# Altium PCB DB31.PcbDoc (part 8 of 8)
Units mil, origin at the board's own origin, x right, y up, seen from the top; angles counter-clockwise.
Board outline 3236.22 x 4456.69 mil, 8 copper layers (Top Layer, MidLayer1, MidLayer2, GND-Layer5, MidLayer3, VCC, MidLayer4, Bottom Layer), stack 61.8 mil thick; 226 components, 469 nets, 1815 pads, 1562 vias.
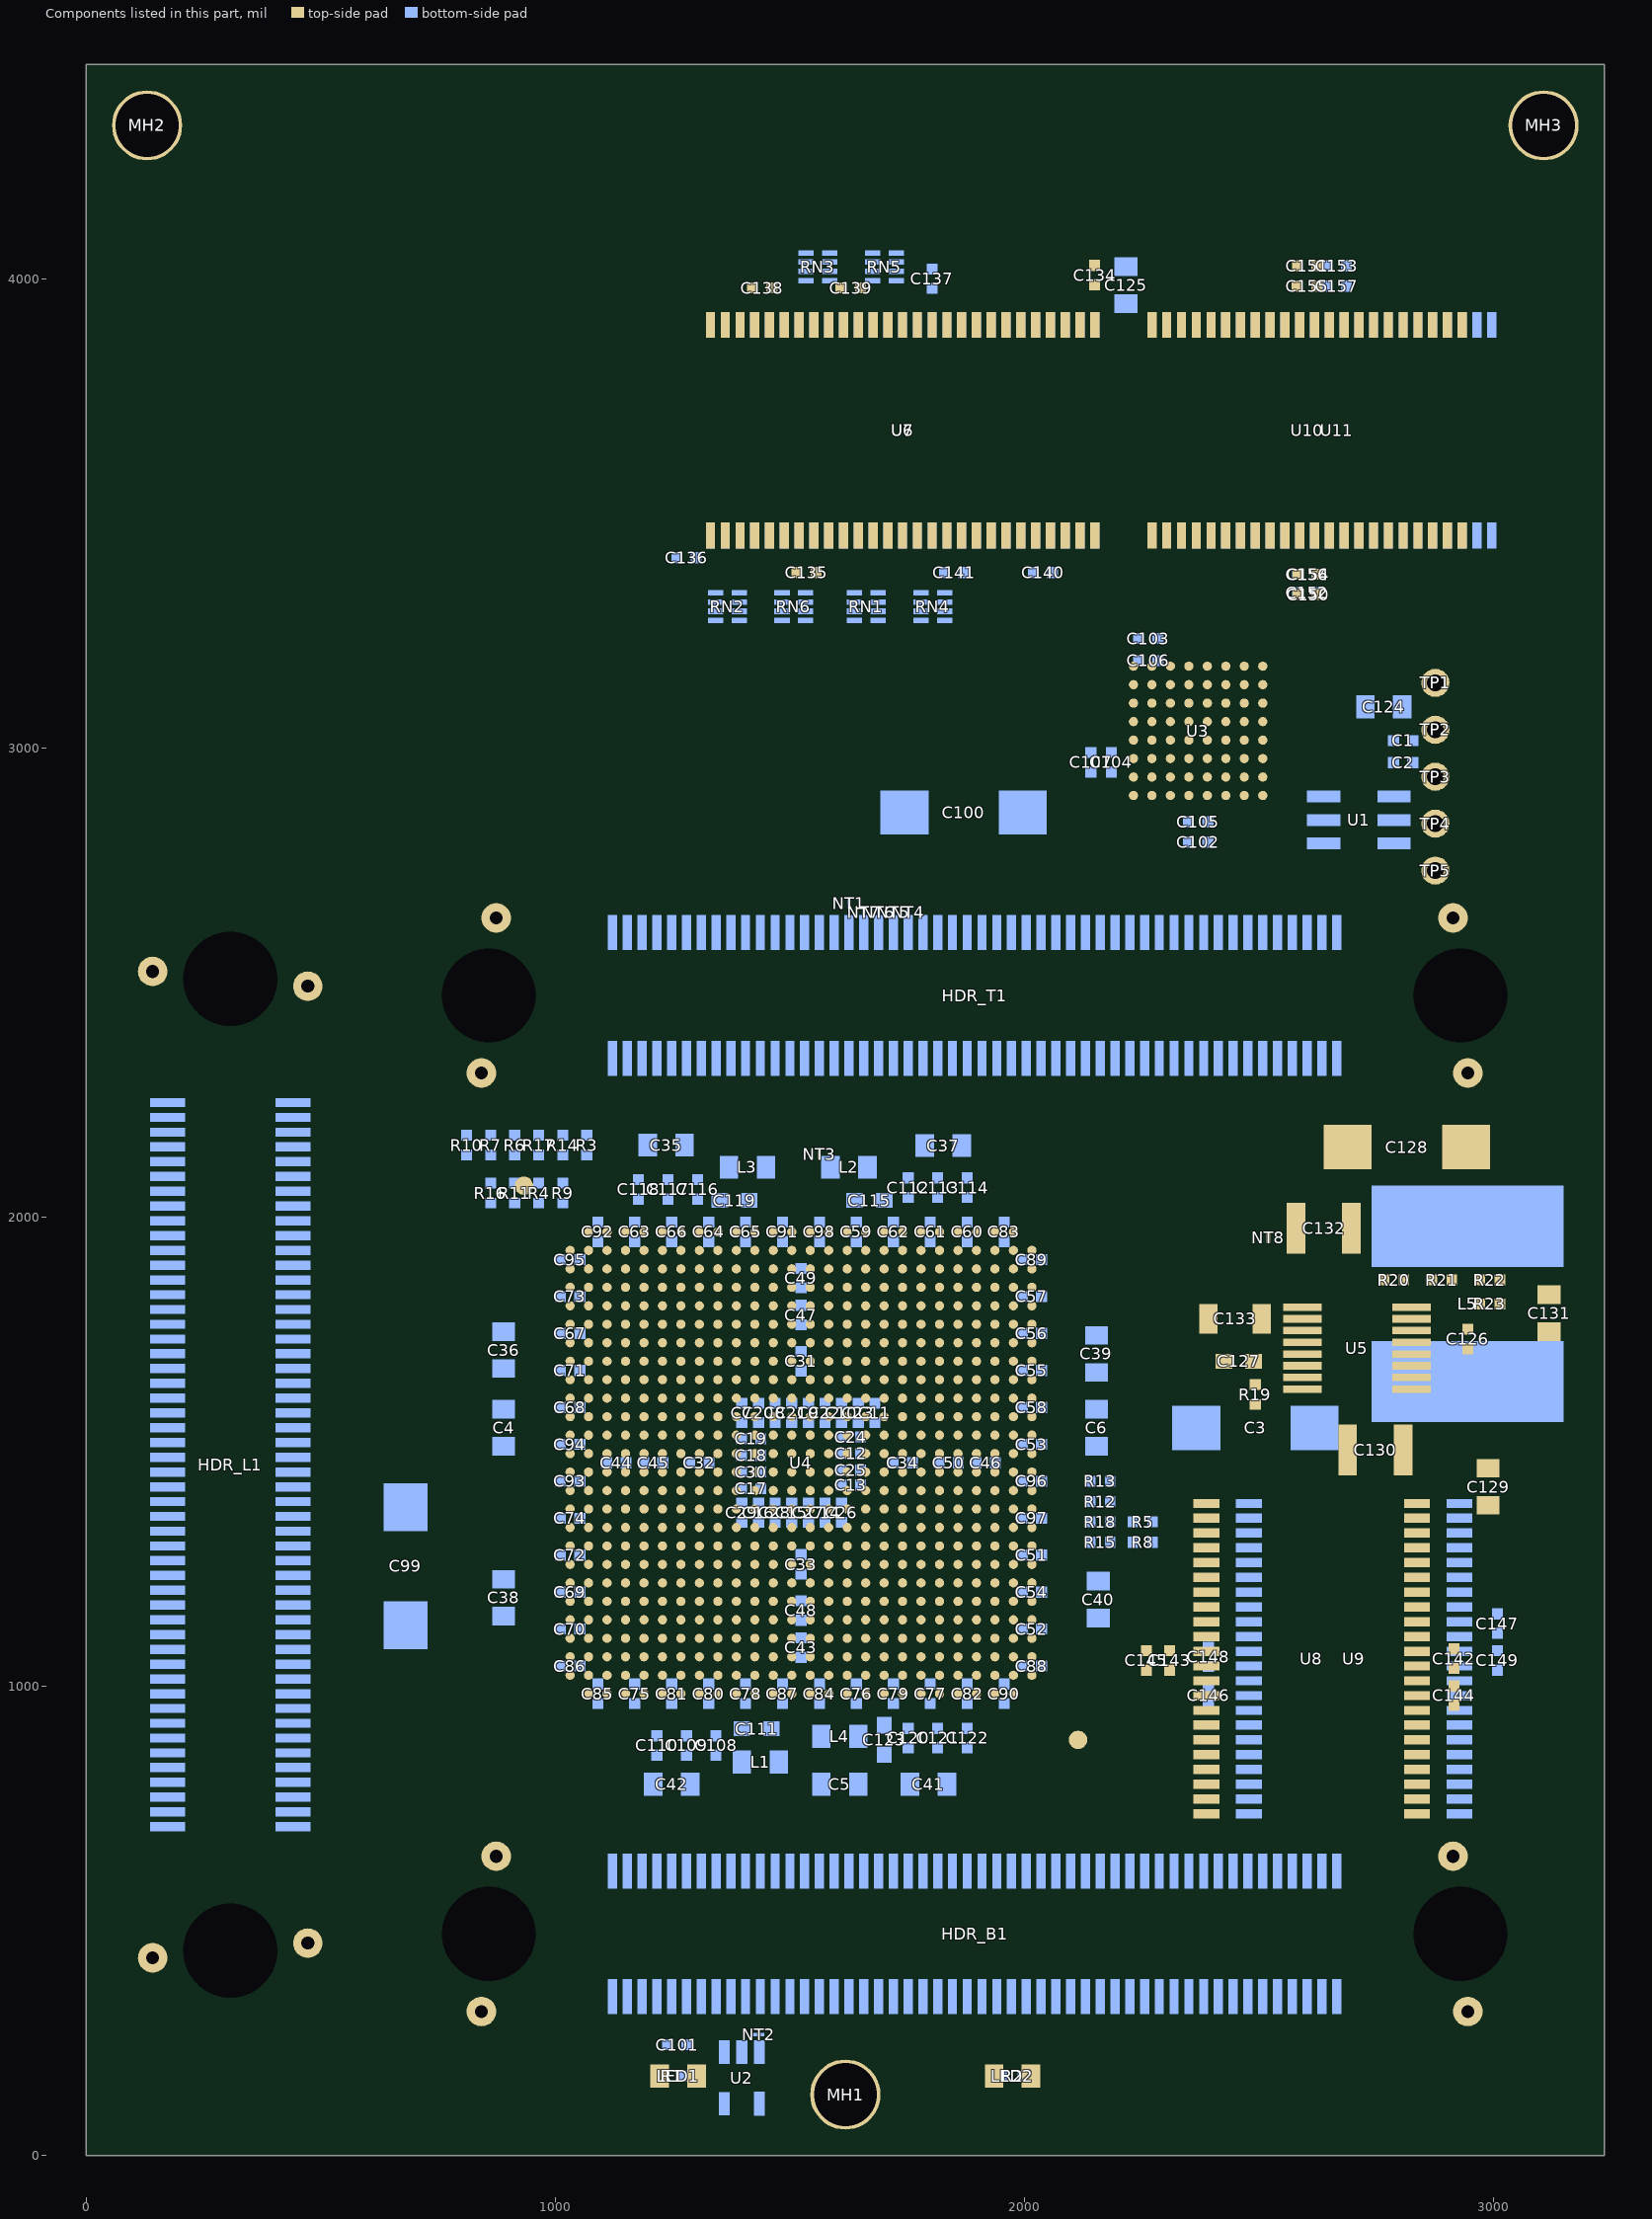
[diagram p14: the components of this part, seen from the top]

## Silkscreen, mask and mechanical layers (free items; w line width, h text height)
Top Overlay:
  region: 146.51,4136.09 139.44,4129.02 164.19,4104.27 171.26,4111.34
  rectangle: 136.51,4026.09 146.51,4136.09
  region: 88.59,4111.34 95.66,4104.27 120.41,4129.02 113.34,4136.09
  region: 123.34,4136.09 113.34,4136.09 113.34,4026.09 123.34,4026.09
  region: 3122.89,4136.09 3115.82,4129.02 3140.56,4104.27 3147.64,4111.34
  rectangle: 3112.89,4026.09 3122.89,4136.09
  region: 3064.97,4111.34 3072.04,4104.27 3096.79,4129.02 3089.71,4136.09
  region: 3099.71,4136.09 3089.71,4136.09 3089.71,4026.09 3099.71,4026.09
  region: 1814.46,159.54 1814.46,169.54 1779.46,169.54 1779.46,159.54
  region: 1772.38,166.61 1779.46,159.54 1857.24,237.33 1850.17,244.4
  rectangle: 1756,183 1766,218
  region: 1840.85,253.71 1833.78,260.78 1756,183 1763.07,175.93
  region: 2787.4,695.23 2787.4,1424.21 2694.88,1424.21 2694.88,695.23
  rectangle: 1337.26,129.92 1351.38,208.66
  rectangle: 2049.67,129.92 2063.98,208.66
  rectangle: 1301.18,3503.94 2179.13,3596.46
  rectangle: 2238.19,3502.95 2966.89,3595.47
  region: 1073.79,617.74 998.77,617.74 998.77,318.48 1073.79,318.48
  rectangle: 2715.79,318.48 2788.79,617.48
  rectangle: 998.77,318.48 1627.79,354.48
  rectangle: 998.77,581.74 1627.79,617.74
  region: 1579.72,4181.1 1579.72,4456.69 1576.77,4456.69 1576.77,4181.1
  region: 1664.37,4181.1 1664.37,4456.69 1649.61,4456.69 1649.61,4181.1
  region: 1640.75,4181.1 1640.75,4456.69 1628.94,4456.69 1628.94,4181.1
  region: 1618.11,4181.1 1618.11,4456.69 1610.24,4456.69 1610.24,4181.1
  region: 1598.43,4181.1 1598.43,4456.69 1593.51,4456.69 1593.51,4181.1
  region: 1689.96,4181.1 1689.96,4456.69 1670.28,4456.69 1670.28,4181.1
  region: 2984.25,4181.1 2984.25,4213.58 1693.9,4213.58 1693.9,4181.1
  region: 2968.5,4438.98 2968.5,4456.69 1693.9,4456.69 1693.9,4438.98
  region: 1803.15,4447.83 1693.9,4447.83 1693.9,4181.1 1803.15,4181.1
  region: 1699.8,4318.9 1699.8,4199.8 1968.5,4199.8 1968.5,4318.9
  rectangle: 2925.2,4181.1 2980.31,4456.69
  rectangle: 2980.31,4181.1 3232.28,4200.79
  rectangle: 2755.91,4204.72 2980.31,4318.9
  rectangle: 2736.22,1620.75 2763.78,1820.75
  lines w3: 1118.09,192.91 1133.09,202.91 1123.09,202.91 1143.09,217.91 ; 1133.09,207.91 1143.09,217.91 ; 1133.09,212.91 1143.09,217.91 ; 2137.52,187.01 2152.52,197.01 2142.52,197.01 2162.52,212.01 ; 2152.52,202.01 2162.52,212.01 ; 2152.52,207.01 2162.52,212.01
  lines w5: 1078.13,171.78 1103.06,171.78 ; 1103.06,173.36 1126.68,173.36 ; 1104.64,163.12 1126.68,172.05 ; 1104.64,180.97 1126.68,172.05 ; 1105.03,168.63 1126.68,172.96 ; 1105.03,175.46 1126.68,171.13 ; 1126.68,156.3 1126.68,187.79 ; 1126.68,171.78 1150.04,171.78 ; 2097.56,165.88 2122.48,165.88 ; 2122.48,167.45 2146.1,167.45 ; 2124.06,157.21 2146.1,166.14 ; 2124.06,175.07 2146.1,166.14 ; 2124.45,162.73 2146.1,167.06 ; 2124.45,169.56 2146.1,165.23 ; 2146.1,150.39 2146.1,181.89 ; 2146.1,165.88 2169.46,165.88 ; 2260.08,1094.39 2280.3,1122.24 ; 2288.68,987.98 2308.9,1015.83 ; 1126.68,172.05 1103.06,187.79 1103.06,156.3 1126.68,172.05 ; 2146.1,166.14 2122.48,150.39 2122.48,181.89 2146.1,166.14
  lines w7.87: 3232.28,4185.04 3232.28,4200.79 ; 3232.28,4200.79 3232.28,4452.76 2980.31,4452.76 2980.31,4200.79 3232.28,4200.79
  text "Altera®  Cyclone™ II" at 1807.26,4342.52 h125.98
  text "EP2C35F672C8" at 1980.49,4216.54 h118.11
  text "SRAM-256Kx16" at 2345.44,3699.95 h50
  text "DRAM-16Mx16" at 1482.53,3682.61 h50
  text "FLASH" at 2491.1,2767.2 h34
  text "1831" at 2721.4,1671.7 h40 r90
  text "SRAM-256Kx16" at 2589.13,807.8 h50 r90
  text "DB31.07" at 1027.8,488.46 h98.43
  text "EP2C35F672C8" at 1027.8,430.47 h60
  text "Altera Daughter Board" at 1028.31,354.49 h60
  text "DB31.07" at 1625.79,318.46 h60
  text "PROGRAM" at 1145,60 h55.12
  text "POWER" at 1895,60 h55.12
Bottom Overlay:
  drawing of 1221 lines, arcs and shapes, not listed
  text "Altera®  Cyclone™ II" at 2905.38,4344.42 h125.98
  text "EP2C35F672C8" at 2732.16,4218.44 h118.11
  text "MANUFACTURE" at 1006.78,3830.86 h40
  text "DATE" at 1007.88,3764.06 h40
  text "SRAM-256Kx16" at 2940.57,3704.01 h50
  text "DRAM-16Mx16" at 1997.78,3682.61 h50
  text "COMPLIANCE:" at 1182.36,3081.45 h45
  text "CLASS 2" at 432.36,2991.45 h40
  text "IPC-A-600H" at 1092.36,2991.45 h40
  text "CLASS 2" at 432.36,2911.45 h40
  text "TYPE 3" at 682.36,2911.45 h40
  text "IPC-6012D" at 1092.36,2911.45 h40
  text "DS2406" at 2711.2,2774.8 h28 r270
  text "1" at 116.93,2272.44 h40
  text "SRAM-256Kx16" at 2733.32,788.17 h50 r270
  text "1" at 1070.87,255.91 h40
  text "DB31" at 412.16,123.67 h120
Bottom Solder:
  region: 2455.79,1920.32 2455.79,2040.32 2305.79,2040.32 2305.79,1920.32
PCB Boundary:
  lines w3.94: 1523.62,4456.69 3236.22,4456.69 ; 1523.62,4456.69 3236.22,4456.69 ; 1523.62,4456.69 0,4456.69 0,0 1618.11,0 3236.22,0 3236.22,4456.69 ; 1523.62,4456.69 3236.22,4456.69 ; 1523.62,4456.69 3236.22,4456.69
Mechanical 7:
  lines w7.87: 2425.71,1720.19 2249.13,1847.52 2249.13,2044.37 2425.71,2171.7 ; 2499.41,1746.69 2322.83,1874.02 2322.83,2070.87 2499.41,2198.19 ; 2575.91,1945.94 2654.65,1945.94 ; 2615.28,1906.57 2615.28,1985.32 ; 2649.61,1972.44 2728.35,1972.44 ; 2688.98,1933.07 2688.98,2011.81 ; 2808.78,1720.19 2985.35,1847.52 2985.35,2044.37 2808.78,2171.7 ; 2882.48,1746.69 3059.06,1874.02 3059.06,2070.87 2882.48,2198.19
Keep Away From Edge:
  lines w7.87: 200,200 3030,200 3030,4250 200,4250 200,200

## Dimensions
307.09,437.01 to 858.27,472.44 on Dimensions
2929.13,472.44 to 2929.13,2472.44 on Dimensions
3106.3,4326.77 to 3236.22,0 on Dimensions
129.92,4342.52 to 0,15.75 on Dimensions
307.09,-15.75 to 0,4275.59 on Dimensions
3236.22,0 to 0,4059.06 on Dimensions
0,4456.69 to -19.69,0 on Dimensions
2929.14,472.44 to 3236.22,-3.94 on Dimensions
1618.11,129.92 to 3236.22,19.69 on Dimensions
307.09,437.01 to -19.69,0 on Dimensions
1618.11,129.92 to 3244.09,0 on Dimensions
2929.14,472.44 to 3244.09,0 on Dimensions
2865.92,4456.69 to 3106.3,4326.77 on Dimensions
